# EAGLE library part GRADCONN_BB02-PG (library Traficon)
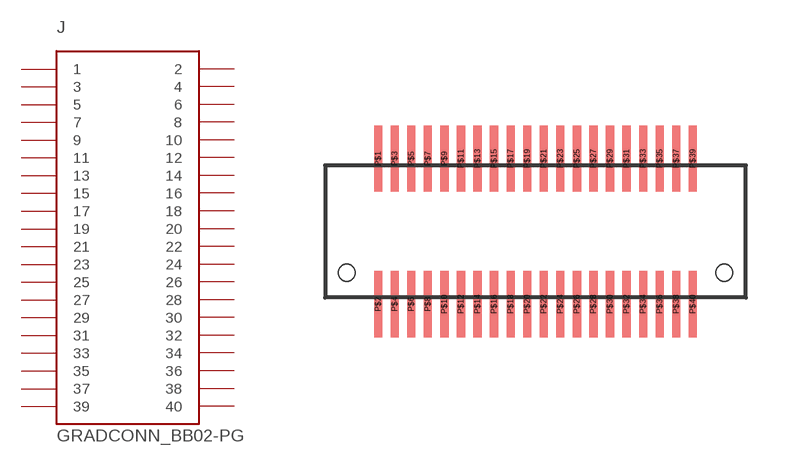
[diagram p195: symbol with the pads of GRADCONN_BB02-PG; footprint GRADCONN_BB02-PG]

Designator prefix J

## GRADCONN_BB02-PG  [GRADCONN_BB02-PG]
P$1  1
P$2  2
P$3  3
P$4  4
P$5  5
P$6  6
P$7  7
P$8  8
P$9  9
P$10  10
P$11  11
P$12  12
P$13  13
P$14  14
P$15  15
P$16  16
P$17  17
P$18  18
P$19  19
P$20  20
P$21  21
P$22  22
P$23  23
P$24  24
P$25  25
P$26  26
P$27  27
P$28  28
P$29  29
P$30  30
P$31  31
P$32  32
P$33  33
P$34  34
P$35  35
P$36  36
P$37  37
P$38  38
P$39  39
P$40  40

## Footprint GRADCONN_BB02-PG (pad centres in mm)
smd 0.25 x 2: P$1 -4.75,2.2; P$2 -4.75,-2.2; P$3 -4.25,2.2; P$4 -4.25,-2.2; P$5 -3.75,2.2; P$6 -3.75,-2.2; P$7 -3.25,2.2; P$8 -3.25,-2.2; P$9 -2.75,2.2; P$10 -2.75,-2.2; P$11 -2.25,2.2; P$12 -2.25,-2.2; P$13 -1.75,2.2; P$14 -1.75,-2.2; P$15 -1.25,2.2; P$16 -1.25,-2.2; P$17 -0.75,2.2; P$18 -0.75,-2.2; P$19 -0.25,2.2; P$20 -0.25,-2.2; P$21 0.25,2.2; P$22 0.25,-2.2; P$23 0.75,2.2; P$24 0.75,-2.2; P$25 1.25,2.2; P$26 1.25,-2.2; P$27 1.75,2.2; P$28 1.75,-2.2; P$29 2.25,2.2; P$30 2.25,-2.2; P$31 2.75,2.2; P$32 2.75,-2.2; P$33 3.25,2.2; P$34 3.25,-2.2; P$35 3.75,2.2; P$36 3.75,-2.2; P$37 4.25,2.2; P$38 4.25,-2.2; P$39 4.75,2.2; P$40 4.75,-2.2
hole 0.5 at -5.7,-1.25
hole 0.5 at 5.7,-1.25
